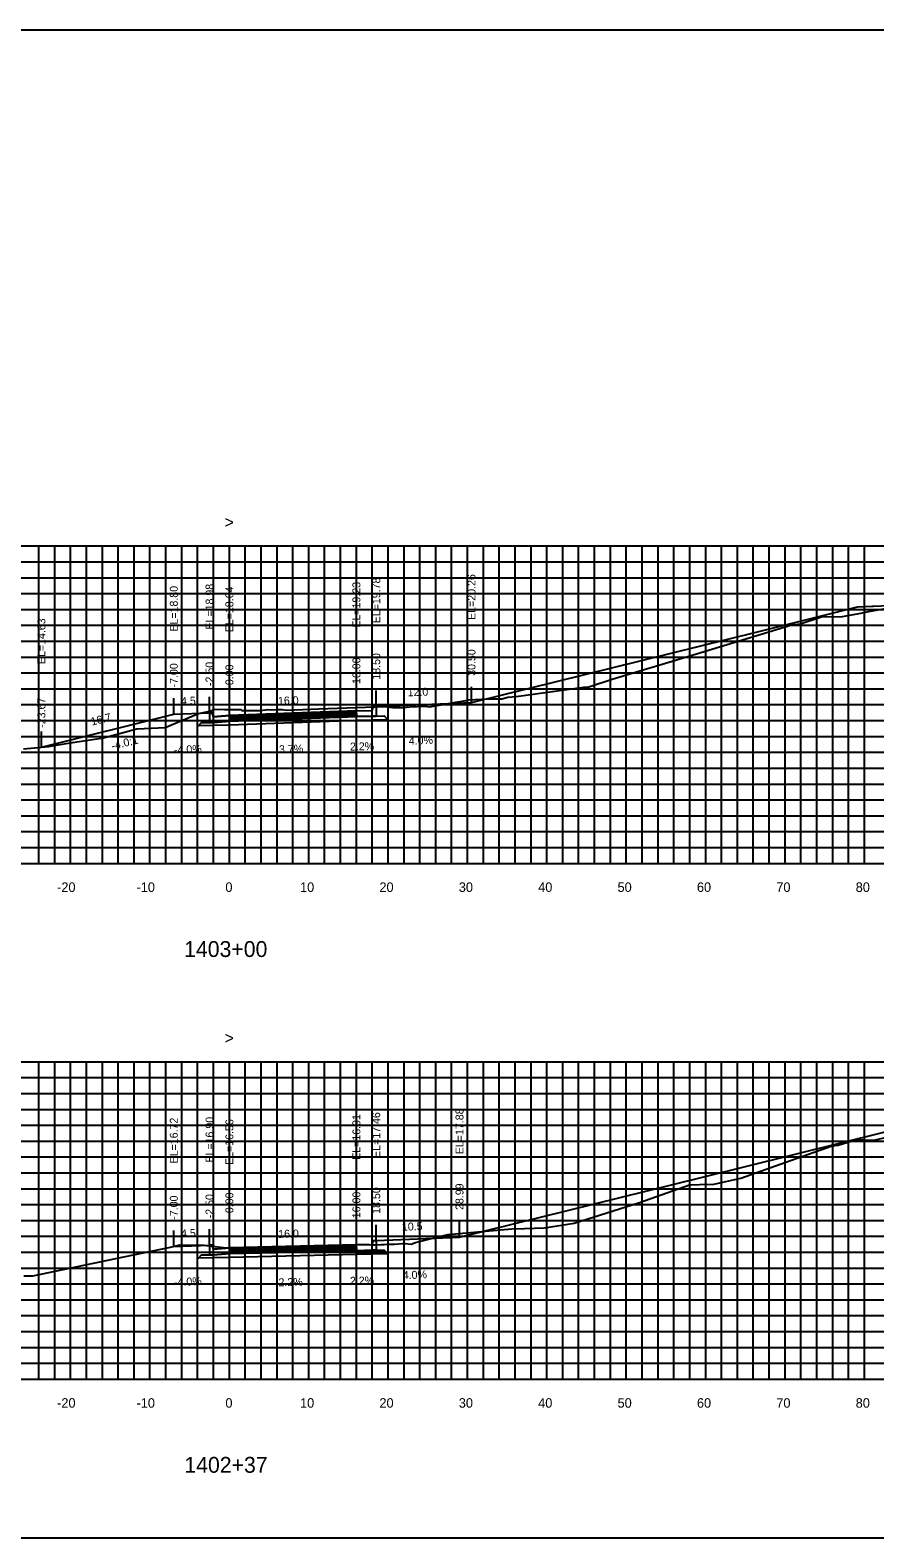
# Model space of a CAD drawing. Extents: x 1797652 to 1804159, y 242516 to 246906.
# Drawn here: x 1802619.4 to 1802725.8, y 242516 to 242706 of the extents above; entities that cross this region are included whole.
import ezdxf

# ---------------------------------------------------------------- set-up
doc = ezdxf.new("R2010")
doc.units = 0
for name, color, linetype in [('1', 7, 'Continuous'), ('10', 7, 'Continuous'), ('2', 7, 'Continuous'), ('3', 7, 'Continuous'), ('4', 7, 'Continuous'), ('60', 7, 'Continuous'), ('BASE', 7, 'Continuous'), ('CL-CNST', 7, 'Continuous'), ('Level 62', 7, 'Continuous'), ('LOWER BINDER', 7, 'Continuous'), ('M-ROADS', 7, 'Continuous'), ('UPPER BINDER', 7, 'Continuous')]:
    doc.layers.add(name, color=color, linetype=linetype)

msp = doc.modelspace()

# ---------------------------------------------------------------- linework, layer by layer
for p, q in [((1802662.99, 242620.78), (1802662.99, 242622.78)), ((1802674.99, 242621.26), (1802674.99, 242623.26)), ((1802637.49, 242619.8), (1802637.49, 242621.8)), ((1802641.99, 242619.98), (1802641.99, 242621.98)), ((1802644.49, 242619.64), (1802644.49, 242621.64)), ((1802660.49, 242620.23), (1802660.49, 242622.23)), ((1802620.81, 242615.63), (1802620.81, 242617.63)), ((1802637.49, 242552.72), (1802637.49, 242554.72)), ((1802641.99, 242552.9), (1802641.99, 242554.9)), ((1802644.49, 242552.56), (1802644.49, 242554.56)), ((1802660.49, 242552.91), (1802660.49, 242554.91)), ((1802662.99, 242553.46), (1802662.99, 242555.46)), ((1802673.48, 242553.88), (1802673.48, 242555.88))]:
    msp.add_line(p, q)
for points in [[(1802494.49, 242516), (1802794.49, 242516), (1802794.49, 242706), (1802494.49, 242706)], [(1802660.49, 242620.23), (1802662.49, 242620.28), (1802662.66, 242620.78), (1802662.99, 242620.78), (1802662.99, 242619.56), (1802662.49, 242619.56), (1802660.49, 242619.51)], [(1802644.49, 242619.64), (1802642.49, 242619.48), (1802642.32, 242619.98), (1802641.99, 242619.98), (1802641.98, 242618.76), (1802642.48, 242618.76), (1802644.49, 242618.92)], [(1802644.49, 242552.56), (1802642.49, 242552.4), (1802642.32, 242552.9), (1802641.99, 242552.9), (1802641.98, 242551.68), (1802642.48, 242551.68), (1802644.49, 242551.84)], [(1802660.49, 242552.91), (1802662.49, 242552.96), (1802662.66, 242553.46), (1802662.99, 242553.46), (1802662.99, 242552.24), (1802662.49, 242552.24), (1802660.49, 242552.19)]]:
    msp.add_lwpolyline(points, close=True)
at = {"layer": '2'}
for points in [[(1802660.49, 242620.08), (1802660.49, 242620.23), (1802644.49, 242619.64), (1802644.49, 242619.49)], [(1802660.49, 242552.76), (1802660.49, 242552.91), (1802644.49, 242552.56), (1802644.49, 242552.41)]]:
    msp.add_lwpolyline(points, close=True, dxfattribs=at)
at = {"layer": '60'}
for p, q in [((1802494.49, 242601), (1802794.49, 242601)), ((1802624.49, 242600.94), (1802624.49, 242601)), ((1802634.49, 242600.94), (1802634.49, 242601)), ((1802644.49, 242600.94), (1802644.49, 242601)), ((1802654.49, 242600.94), (1802654.49, 242601)), ((1802664.49, 242600.94), (1802664.49, 242601)), ((1802674.49, 242600.94), (1802674.49, 242601)), ((1802684.49, 242600.94), (1802684.49, 242601)), ((1802694.49, 242600.94), (1802694.49, 242601)), ((1802704.49, 242600.94), (1802704.49, 242601)), ((1802714.49, 242600.94), (1802714.49, 242601)), ((1802724.49, 242600.94), (1802724.49, 242601)), ((1802494.49, 242536), (1802794.49, 242536)), ((1802624.49, 242535.94), (1802624.49, 242536)), ((1802634.49, 242535.94), (1802634.49, 242536)), ((1802644.49, 242535.94), (1802644.49, 242536)), ((1802654.49, 242535.94), (1802654.49, 242536)), ((1802664.49, 242535.94), (1802664.49, 242536)), ((1802674.49, 242535.94), (1802674.49, 242536)), ((1802684.49, 242535.94), (1802684.49, 242536)), ((1802694.49, 242535.94), (1802694.49, 242536)), ((1802704.49, 242535.94), (1802704.49, 242536)), ((1802714.49, 242535.94), (1802714.49, 242536)), ((1802724.49, 242535.94), (1802724.49, 242536))]:
    msp.add_line(p, q, dxfattribs=at)
at = {"layer": 'BASE'}
for points in [[(1802644.49, 242618.92), (1802660.49, 242619.51), (1802662.49, 242619.56), (1802662.99, 242619.56), (1802663.99, 242619.58), (1802664.47, 242619.1), (1802660.49, 242619.01), (1802644.49, 242618.42), (1802640.58, 242618.34), (1802640.98, 242618.74), (1802641.98, 242618.76), (1802642.48, 242618.76)], [(1802644.49, 242551.84), (1802660.49, 242552.19), (1802662.49, 242552.24), (1802662.99, 242552.24), (1802663.99, 242552.26), (1802664.47, 242551.78), (1802660.49, 242551.69), (1802644.49, 242551.34), (1802640.58, 242551.25), (1802640.98, 242551.66), (1802641.98, 242551.68), (1802642.48, 242551.68)]]:
    msp.add_lwpolyline(points, close=True, dxfattribs=at)
at = {"layer": 'CL-CNST'}
for points in [[(1802674.99, 242621.26), (1802710.86, 242630.15), (1802723.62, 242633.31), (1802725.45, 242633.4), (1802725.64, 242633.41), (1802733.38, 242633.76), (1802734.66, 242633.82), (1802734.73, 242633.89), (1802734.74, 242633.9), (1802734.9, 242633.91), (1802735.76, 242633.94), (1802737.81, 242634.04), (1802747.89, 242634.5), (1802756.56, 242634.9), (1802760.03, 242635.06), (1802764.06, 242635.25), (1802772.17, 242635.62), (1802779.15, 242635.94), (1802784.31, 242636.18), (1802790.28, 242636.45), (1802794.49, 242636.65)], [(1802620.81, 242615.63), (1802637.49, 242619.8), (1802641.99, 242619.98), (1802642.32, 242619.98), (1802642.49, 242619.48), (1802644.49, 242619.64), (1802660.49, 242620.23), (1802662.49, 242620.28), (1802662.66, 242620.78), (1802662.99, 242620.78), (1802674.99, 242621.26)], [(1802673.48, 242553.88), (1802703.92, 242561.43), (1802732.86, 242568.6), (1802734.25, 242568.67), (1802734.88, 242568.7), (1802737.48, 242568.81), (1802743.88, 242569.11), (1802743.94, 242569.17), (1802743.96, 242569.19), (1802744.22, 242569.2), (1802744.97, 242569.23), (1802747.78, 242569.36), (1802757.09, 242569.78), (1802759.14, 242569.87), (1802769.2, 242570.33), (1802780.7, 242570.86), (1802781.32, 242570.89), (1802781.86, 242570.91), (1802790.1, 242571.29), (1802793.23, 242571.43), (1802793.43, 242571.44), (1802794.49, 242571.49)], [(1802637.49, 242552.72), (1802641.99, 242552.9), (1802642.32, 242552.9), (1802642.49, 242552.4), (1802644.49, 242552.56), (1802660.49, 242552.91), (1802662.49, 242552.96), (1802662.66, 242553.46), (1802662.99, 242553.46), (1802673.48, 242553.88)]]:
    msp.add_lwpolyline(points, dxfattribs=at)
at = {"layer": 'Level 62'}
for p, q in [((1802494.49, 242641), (1802794.49, 242641)), ((1802620.49, 242601), (1802620.49, 242641)), ((1802622.49, 242601), (1802622.49, 242641)), ((1802624.49, 242601), (1802624.49, 242641)), ((1802626.49, 242601), (1802626.49, 242641)), ((1802628.49, 242601), (1802628.49, 242641)), ((1802630.49, 242601), (1802630.49, 242641)), ((1802632.49, 242601), (1802632.49, 242641)), ((1802634.49, 242601), (1802634.49, 242641)), ((1802636.49, 242601), (1802636.49, 242641)), ((1802638.49, 242601), (1802638.49, 242641)), ((1802640.49, 242601), (1802640.49, 242641)), ((1802642.49, 242601), (1802642.49, 242641)), ((1802644.49, 242601), (1802644.49, 242641)), ((1802646.49, 242601), (1802646.49, 242641)), ((1802648.49, 242601), (1802648.49, 242641)), ((1802650.49, 242601), (1802650.49, 242641)), ((1802652.49, 242601), (1802652.49, 242641)), ((1802654.49, 242601), (1802654.49, 242641)), ((1802656.49, 242601), (1802656.49, 242641)), ((1802658.49, 242601), (1802658.49, 242641)), ((1802660.49, 242601), (1802660.49, 242641)), ((1802662.49, 242601), (1802662.49, 242641)), ((1802664.49, 242601), (1802664.49, 242641)), ((1802666.49, 242601), (1802666.49, 242641)), ((1802668.49, 242601), (1802668.49, 242641)), ((1802670.49, 242601), (1802670.49, 242641)), ((1802672.49, 242601), (1802672.49, 242641)), ((1802674.49, 242601), (1802674.49, 242641)), ((1802676.49, 242601), (1802676.49, 242641)), ((1802678.49, 242601), (1802678.49, 242641)), ((1802680.49, 242601), (1802680.49, 242641)), ((1802682.49, 242601), (1802682.49, 242641)), ((1802684.49, 242601), (1802684.49, 242641)), ((1802686.49, 242601), (1802686.49, 242641)), ((1802688.49, 242601), (1802688.49, 242641)), ((1802690.49, 242601), (1802690.49, 242641)), ((1802692.49, 242601), (1802692.49, 242641)), ((1802694.49, 242601), (1802694.49, 242641)), ((1802696.49, 242601), (1802696.49, 242641)), ((1802698.49, 242601), (1802698.49, 242641)), ((1802700.49, 242601), (1802700.49, 242641)), ((1802702.49, 242601), (1802702.49, 242641)), ((1802704.49, 242601), (1802704.49, 242641)), ((1802706.49, 242601), (1802706.49, 242641)), ((1802708.49, 242601), (1802708.49, 242641)), ((1802710.49, 242601), (1802710.49, 242641)), ((1802712.49, 242601), (1802712.49, 242641)), ((1802714.49, 242601), (1802714.49, 242641)), ((1802716.49, 242601), (1802716.49, 242641)), ((1802718.49, 242601), (1802718.49, 242641)), ((1802720.49, 242601), (1802720.49, 242641)), ((1802722.49, 242601), (1802722.49, 242641)), ((1802724.49, 242601), (1802724.49, 242641)), ((1802494.49, 242639), (1802794.49, 242639)), ((1802494.49, 242637), (1802794.49, 242637)), ((1802494.49, 242635), (1802794.49, 242635)), ((1802494.49, 242633), (1802794.49, 242633)), ((1802494.49, 242631), (1802794.49, 242631)), ((1802494.49, 242629), (1802794.49, 242629)), ((1802494.49, 242627), (1802794.49, 242627)), ((1802494.49, 242625), (1802794.49, 242625)), ((1802494.49, 242623), (1802794.49, 242623)), ((1802494.49, 242621), (1802794.49, 242621)), ((1802494.49, 242619), (1802794.49, 242619)), ((1802494.49, 242617), (1802794.49, 242617)), ((1802494.49, 242615), (1802794.49, 242615)), ((1802494.49, 242613), (1802794.49, 242613)), ((1802494.49, 242611), (1802794.49, 242611)), ((1802494.49, 242609), (1802794.49, 242609)), ((1802494.49, 242607), (1802794.49, 242607)), ((1802494.49, 242605), (1802794.49, 242605)), ((1802494.49, 242603), (1802794.49, 242603)), ((1802494.49, 242601), (1802794.49, 242601)), ((1802494.49, 242576), (1802794.49, 242576)), ((1802620.49, 242536), (1802620.49, 242576)), ((1802622.49, 242536), (1802622.49, 242576)), ((1802624.49, 242536), (1802624.49, 242576)), ((1802626.49, 242536), (1802626.49, 242576)), ((1802628.49, 242536), (1802628.49, 242576)), ((1802630.49, 242536), (1802630.49, 242576)), ((1802632.49, 242536), (1802632.49, 242576)), ((1802634.49, 242536), (1802634.49, 242576)), ((1802636.49, 242536), (1802636.49, 242576)), ((1802638.49, 242536), (1802638.49, 242576)), ((1802640.49, 242536), (1802640.49, 242576)), ((1802642.49, 242536), (1802642.49, 242576)), ((1802644.49, 242536), (1802644.49, 242576)), ((1802646.49, 242536), (1802646.49, 242576)), ((1802648.49, 242536), (1802648.49, 242576)), ((1802650.49, 242536), (1802650.49, 242576)), ((1802652.49, 242536), (1802652.49, 242576)), ((1802654.49, 242536), (1802654.49, 242576)), ((1802656.49, 242536), (1802656.49, 242576)), ((1802658.49, 242536), (1802658.49, 242576)), ((1802660.49, 242536), (1802660.49, 242576)), ((1802662.49, 242536), (1802662.49, 242576)), ((1802664.49, 242536), (1802664.49, 242576)), ((1802666.49, 242536), (1802666.49, 242576)), ((1802668.49, 242536), (1802668.49, 242576)), ((1802670.49, 242536), (1802670.49, 242576)), ((1802672.49, 242536), (1802672.49, 242576)), ((1802674.49, 242536), (1802674.49, 242576)), ((1802676.49, 242536), (1802676.49, 242576)), ((1802678.49, 242536), (1802678.49, 242576)), ((1802680.49, 242536), (1802680.49, 242576)), ((1802682.49, 242536), (1802682.49, 242576)), ((1802684.49, 242536), (1802684.49, 242576)), ((1802686.49, 242536), (1802686.49, 242576)), ((1802688.49, 242536), (1802688.49, 242576)), ((1802690.49, 242536), (1802690.49, 242576)), ((1802692.49, 242536), (1802692.49, 242576)), ((1802694.49, 242536), (1802694.49, 242576)), ((1802696.49, 242536), (1802696.49, 242576)), ((1802698.49, 242536), (1802698.49, 242576)), ((1802700.49, 242536), (1802700.49, 242576)), ((1802702.49, 242536), (1802702.49, 242576)), ((1802704.49, 242536), (1802704.49, 242576)), ((1802706.49, 242536), (1802706.49, 242576)), ((1802708.49, 242536), (1802708.49, 242576)), ((1802710.49, 242536), (1802710.49, 242576)), ((1802712.49, 242536), (1802712.49, 242576)), ((1802714.49, 242536), (1802714.49, 242576)), ((1802716.49, 242536), (1802716.49, 242576)), ((1802718.49, 242536), (1802718.49, 242576)), ((1802720.49, 242536), (1802720.49, 242576)), ((1802722.49, 242536), (1802722.49, 242576)), ((1802724.49, 242536), (1802724.49, 242576)), ((1802494.49, 242574), (1802794.49, 242574)), ((1802494.49, 242572), (1802794.49, 242572)), ((1802494.49, 242570), (1802794.49, 242570)), ((1802494.49, 242568), (1802794.49, 242568)), ((1802494.49, 242566), (1802794.49, 242566)), ((1802494.49, 242564), (1802794.49, 242564)), ((1802494.49, 242562), (1802794.49, 242562)), ((1802494.49, 242560), (1802794.49, 242560)), ((1802494.49, 242558), (1802794.49, 242558)), ((1802494.49, 242556), (1802794.49, 242556)), ((1802494.49, 242554), (1802794.49, 242554)), ((1802494.49, 242552), (1802794.49, 242552)), ((1802494.49, 242550), (1802794.49, 242550)), ((1802494.49, 242548), (1802794.49, 242548)), ((1802494.49, 242546), (1802794.49, 242546)), ((1802494.49, 242544), (1802794.49, 242544)), ((1802494.49, 242542), (1802794.49, 242542)), ((1802494.49, 242540), (1802794.49, 242540)), ((1802494.49, 242538), (1802794.49, 242538)), ((1802494.49, 242536), (1802794.49, 242536))]:
    msp.add_line(p, q, dxfattribs=at)
at = {"layer": 'LOWER BINDER'}
for points in [[(1802644.49, 242619.11), (1802644.49, 242619.3), (1802660.49, 242619.89), (1802660.49, 242619.7)], [(1802644.49, 242618.92), (1802644.49, 242619.11), (1802660.49, 242619.7), (1802660.49, 242619.51)], [(1802644.49, 242552.03), (1802644.49, 242552.22), (1802660.49, 242552.57), (1802660.49, 242552.38)], [(1802644.49, 242551.84), (1802644.49, 242552.03), (1802660.49, 242552.38), (1802660.49, 242552.19)]]:
    msp.add_lwpolyline(points, close=True, dxfattribs=at)
at = {"layer": 'M-ROADS'}
for points in [[(1802618.55, 242615.45), (1802621.76, 242615.71), (1802622.4, 242615.85), (1802623.91, 242616.11), (1802624.71, 242616.23), (1802628.63, 242616.81), (1802632.83, 242617.96), (1802633.74, 242618), (1802636.42, 242618.13), (1802640.59, 242619.88), (1802642.01, 242620.18), (1802642.67, 242620.44), (1802643.87, 242620.37), (1802645.08, 242620.39), (1802645.93, 242620.4), (1802646.04, 242620.28), (1802647.08, 242620.25), (1802647.1, 242620.25), (1802648.25, 242620.27), (1802648.33, 242620.25), (1802648.37, 242620.26), (1802649.39, 242620.39), (1802649.82, 242620.36), (1802650.47, 242620.4), (1802651.16, 242620.4), (1802651.68, 242620.32), (1802655.75, 242620.48), (1802664.01, 242620.77), (1802665.07, 242620.62), (1802665.14, 242620.62), (1802665.43, 242620.64), (1802666.37, 242620.66), (1802666.45, 242620.66), (1802666.53, 242620.66), (1802667.48, 242620.77), (1802667.75, 242620.74), (1802668.56, 242620.79), (1802669.09, 242620.8), (1802669.74, 242620.71), (1802673.28, 242621.35), (1802674.29, 242621.53), (1802674.62, 242621.59), (1802677.09, 242621.74), (1802678.34, 242621.74), (1802678.81, 242621.74), (1802679.58, 242621.95), (1802680.62, 242622.03), (1802689.15, 242623.21), (1802689.65, 242623.21), (1802692.83, 242624.25), (1802702.35, 242627.1), (1802715.36, 242631.07), (1802716.4, 242631.17), (1802719.09, 242632.08), (1802721.73, 242632.1), (1802724.03, 242632.53), (1802725.27, 242632.77), (1802727.88, 242633.26)], [(1802618.59, 242549.02), (1802619.74, 242549.03), (1802630.2, 242551.21), (1802637.08, 242552.62), (1802638.25, 242552.92), (1802638.73, 242552.87), (1802639.16, 242552.89), (1802640.51, 242552.87), (1802640.55, 242552.87), (1802641.16, 242552.9), (1802641.26, 242552.9), (1802641.27, 242552.9), (1802641.29, 242552.89), (1802643.77, 242552.61), (1802644.38, 242552.55), (1802644.96, 242552.57), (1802645.56, 242552.58), (1802646.13, 242552.52), (1802646.39, 242552.52), (1802647.21, 242552.59), (1802647.86, 242552.51), (1802648.29, 242552.53), (1802649.17, 242552.6), (1802649.5, 242552.56), (1802652.59, 242552.68), (1802661.67, 242553.03), (1802662.62, 242552.92), (1802662.82, 242552.93), (1802663.55, 242552.96), (1802663.97, 242552.98), (1802664.33, 242552.99), (1802664.63, 242552.99), (1802665.15, 242553.03), (1802665.31, 242553.02), (1802666.24, 242553.08), (1802666.68, 242553.08), (1802667.41, 242552.99), (1802667.93, 242553.23), (1802671.99, 242554.22), (1802680.08, 242554.93), (1802681.67, 242554.98), (1802684.2, 242555.06), (1802687.92, 242555.67), (1802696.14, 242558.28), (1802702.45, 242560.49), (1802703.73, 242560.51), (1802705.52, 242560.55), (1802708.93, 242561.32), (1802715.91, 242563.8), (1802720.44, 242565.42), (1802721.19, 242565.47), (1802723.51, 242566.2), (1802725.72, 242566.13), (1802733.03, 242567.84)]]:
    msp.add_lwpolyline(points, dxfattribs=at)
at = {"layer": 'UPPER BINDER'}
for points in [[(1802660.49, 242619.89), (1802660.49, 242620.08), (1802644.49, 242619.49), (1802644.49, 242619.3)], [(1802660.49, 242552.57), (1802660.49, 242552.76), (1802644.49, 242552.41), (1802644.49, 242552.22)]]:
    msp.add_lwpolyline(points, close=True, dxfattribs=at)

# ---------------------------------------------------------------- texts
msp.add_text('-4.0:1', height=1, rotation=14.0362).set_placement((1802629.76, 242615.29))
at = {"layer": '1'}
for s, p in [('1403+00', (1802638.79, 242589.2)), ('1402+37', (1802638.82, 242524.2))]:
    msp.add_text(s, height=2, dxfattribs=at).set_placement(p)
at = {"layer": '10'}
for s, p in [('-20', (1802622.79, 242597.4)), ('-10', (1802632.79, 242597.4)), ('0', (1802643.99, 242597.4)), ('10', (1802653.39, 242597.4)), ('20', (1802663.39, 242597.4)), ('30', (1802673.39, 242597.4)), ('40', (1802683.39, 242597.4)), ('50', (1802693.39, 242597.4)), ('60', (1802703.39, 242597.4)), ('70', (1802713.39, 242597.4)), ('80', (1802723.39, 242597.4)), ('-20', (1802622.79, 242532.4)), ('-10', (1802632.79, 242532.4)), ('0', (1802643.99, 242532.4)), ('10', (1802653.39, 242532.4)), ('20', (1802663.39, 242532.4)), ('30', (1802673.39, 242532.4)), ('40', (1802683.39, 242532.4)), ('50', (1802693.39, 242532.4)), ('60', (1802703.39, 242532.4)), ('70', (1802713.39, 242532.4)), ('80', (1802723.39, 242532.4))]:
    msp.add_text(s, height=1.2, dxfattribs=at).set_placement(p)
at = {"layer": '3'}
for s, p in [('EL=18.80', (1802637.99, 242630.2)), ('EL=18.98', (1802642.49, 242630.46)), ('EL=18.64', (1802644.99, 242630.12)), ('EL=19.23', (1802660.99, 242630.7)), ('EL=19.78', (1802663.49, 242631.25)), ('EL=20.26', (1802675.49, 242631.68)), ('EL=14.63', (1802621.31, 242626.11)), ('-2.50', (1802642.49, 242623.35)), ('16.00', (1802660.99, 242623.6)), ('18.50', (1802663.49, 242624.15)), ('30.50', (1802675.49, 242624.63)), ('-7.00', (1802637.99, 242623.17)), ('-0.00', (1802644.99, 242623.01)), ('-23.67', (1802621.31, 242618.09)), ('EL=16.91', (1802660.99, 242563.64)), ('EL=17.46', (1802663.49, 242563.88)), ('EL=17.88', (1802673.98, 242564.35)), ('EL=16.72', (1802637.99, 242563.19)), ('EL=16.90', (1802642.49, 242563.29)), ('EL=16.56', (1802644.99, 242562.99)), ('18.50', (1802663.49, 242556.83)), ('28.99', (1802673.98, 242557.32)), ('-7.00', (1802637.99, 242556.09)), ('-2.50', (1802642.49, 242556.27)), ('0.00', (1802644.99, 242556.92)), ('16.00', (1802660.99, 242556.28))]:
    msp.add_text(s, height=1, rotation=90, dxfattribs=at).set_placement(p)
at = {"layer": '4'}
for s, rotation, p in [('12.0', 2.2906, (1802666.96, 242622.04)), ('4.5', 2.2906, (1802638.42, 242620.94)), ('16.0', 2.1089, (1802650.63, 242620.97)), ('16.7', 14.0362, (1802627.16, 242618.35)), ('4.0%', 2.2906, (1802667.11, 242615.94)), ('-4.0%', 2.2906, (1802637.53, 242614.8)), ('3.7%', 2.1089, (1802650.76, 242614.87)), ('2.2%', 1.2603, (1802659.69, 242615.21)), ('4.5', 2.2906, (1802638.42, 242553.86)), ('16.0', 1.2603, (1802650.65, 242553.8)), ('10.5', 2.2906, (1802666.24, 242554.69)), ('-4.0%', 2.2906, (1802637.53, 242547.72)), ('2.2%', 1.2603, (1802650.69, 242547.7)), ('2.2%', 1.2603, (1802659.69, 242547.89)), ('4.0%', 2.2906, (1802666.35, 242548.59))]:
    msp.add_text(s, height=1, rotation=rotation, dxfattribs=at).set_placement(p)
at = {"layer": '60'}
for p in [(1802643.88, 242643.25), (1802643.88, 242578.25)]:
    msp.add_text('>', height=1.5, dxfattribs=at).set_placement(p)

doc.saveas('drawing.dxf')
